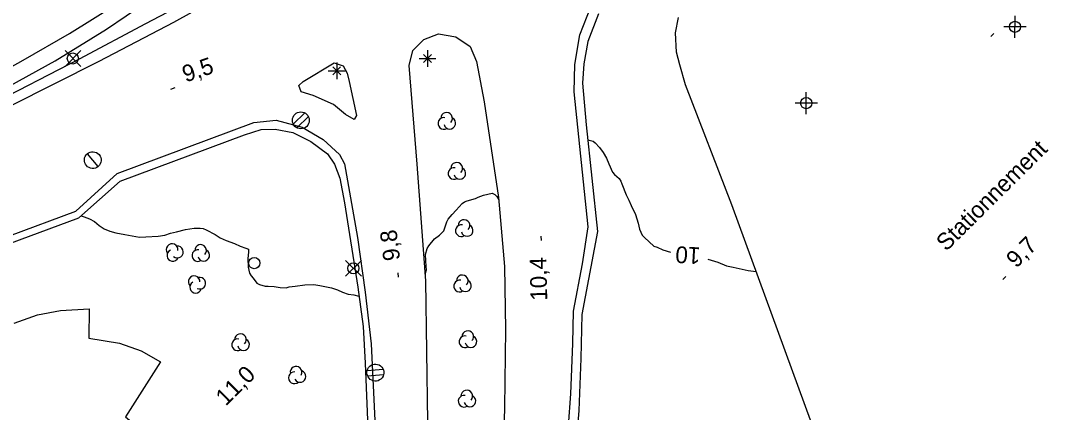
# Model space of a CAD drawing. Extents: x 381879 to 384696, y 5564785 to 5567594.
# Drawn here: x 383815.6 to 384000, y 5566230.8 to 5566301.1 of the extents above; entities that cross this region are included whole.
import ezdxf

# ---------------------------------------------------------------- set-up
doc = ezdxf.new("R2010")
doc.units = 0
for name, color, linetype in [('Niveau 1', 7, 'Continuous'), ('Niveau 21', 7, 'Continuous'), ('Niveau 22', 7, 'Continuous'), ('Niveau 3', 7, 'Continuous'), ('Niveau 31', 7, 'Continuous'), ('Niveau 36', 7, 'Continuous'), ('Niveau 44', 7, 'Continuous'), ('Niveau 52', 7, 'Continuous')]:
    doc.layers.add(name, color=color, linetype=linetype)

msp = doc.modelspace()

# ---------------------------------------------------------------- linework, layer by layer
at = {"layer": 'Niveau 1'}
for points in [[(383917.33, 5566279.72), (383918.3, 5566279.5), (383918.69, 5566279.18), (383919.44, 5566278.36), (383920.13, 5566277.45), (383920.72, 5566276.45), (383921.1, 5566275.41), (383921.8, 5566273.92), (383922.16, 5566273.52), (383922.96, 5566272.79), (383923.25, 5566272.33), (383923.44, 5566271.8), (383924.24, 5566269.83), (383924.73, 5566268.92), (383925.13, 5566267.94), (383925.88, 5566266.36), (383926.41, 5566264.76), (383926.62, 5566263.72), (383927.12, 5566262.62), (383927.54, 5566262.2), (383929.22, 5566260.67), (383929.8, 5566260.49), (383930.81, 5566259.99), (383932.18, 5566259.6)], [(383888.19, 5566255.61), (383888.39, 5566256.4), (383888.33, 5566257), (383888.24, 5566259.19), (383888.53, 5566260.23), (383888.81, 5566260.69), (383889.85, 5566261.95), (383890.75, 5566262.65), (383891.52, 5566263.43), (383891.72, 5566263.94), (383892.05, 5566265.01), (383892.32, 5566265.49), (383893, 5566266.32), (383893.75, 5566267.09), (383894.8, 5566268.29), (383895.22, 5566268.59), (383895.73, 5566268.77), (383897.22, 5566269.18), (383897.67, 5566269.42), (383898.66, 5566269.78), (383900.19, 5566270.17), (383900.69, 5566269.94), (383901.03, 5566269.53), (383901.4, 5566268.96)], [(383826.48, 5566266.07), (383826.99, 5566265.94), (383828, 5566265.54), (383828.87, 5566265.05), (383829.71, 5566264.35), (383830.59, 5566263.79), (383831.63, 5566263.34), (383832.67, 5566263.05), (383834.31, 5566262.73), (383836.97, 5566262.28), (383838.08, 5566262.31), (383840.26, 5566262.42), (383841.48, 5566262.63), (383842.52, 5566262.97), (383843.56, 5566263.2), (383845.19, 5566263.64), (383846.74, 5566263.89), (383847.82, 5566263.91), (383848.37, 5566263.81), (383848.89, 5566263.58), (383850.52, 5566262.76), (383851.42, 5566262.15), (383852.5, 5566261.7), (383853.98, 5566261.15), (383854.97, 5566260.66), (383856.04, 5566260.32), (383856.49, 5566260.1), (383856.47, 5566259.6), (383856.35, 5566258.47), (383856.45, 5566256.88), (383856.68, 5566255.83), (383856.97, 5566255.32), (383857.31, 5566254.92), (383857.98, 5566254.02), (383858.46, 5566253.78), (383859.48, 5566253.46), (383860.02, 5566253.48), (383861.1, 5566253.4), (383862.18, 5566253.23), (383863.26, 5566253.21), (383863.78, 5566253.35), (383864.85, 5566253.47), (383866.59, 5566253.74), (383868.22, 5566253.78), (383869.28, 5566253.6), (383871.4, 5566253.17), (383872.44, 5566252.81), (383873.38, 5566252.38), (383874.38, 5566252.07), (383875.41, 5566251.92), (383876.31, 5566251.7)], [(383938.9, 5566258.31), (383940.66, 5566257.8), (383942.21, 5566257.15), (383943.41, 5566256.88), (383946.12, 5566256.32), (383947.55, 5566256.14)]]:
    msp.add_lwpolyline(points, dxfattribs=at)
at = {"layer": 'Niveau 21'}
for p, q in [((383887.1, 5566294.3), (383890.1, 5566294.3)), ((383887.88, 5566293.58), (383889.3, 5566295)), ((383889.32, 5566293.6), (383887.88, 5566295)), ((383888.6, 5566295.8), (383888.6, 5566292.8)), ((383871.59, 5566291.38), (383873.01, 5566292.8)), ((383873.03, 5566291.4), (383871.59, 5566292.8)), ((383872.31, 5566293.6), (383872.31, 5566290.6)), ((383870.81, 5566292.1), (383873.81, 5566292.1))]:
    msp.add_line(p, q, dxfattribs=at)
for points in [[(383915.3, 5566106.7), (383911.13, 5566107.33), (383907.59, 5566109.64), (383905.66, 5566111.96), (383904.48, 5566114.9), (383904.17, 5566117.91), (383904.87, 5566125.53), (383908.96, 5566171.44), (383912.18, 5566208.66), (383913.49, 5566222.72), (383914.28, 5566234.18), (383914.69, 5566243.23), (383914.76, 5566249), (383916.38, 5566257.46), (383917.43, 5566264.12), (383914.93, 5566288.3), (383915.05, 5566293.22), (383915.95, 5566298.53), (383917.89, 5566303.54), (383922.17, 5566309.93), (383926.92, 5566314.19)], [(383813.8, 5566285.8), (383829.7, 5566293.8), (383843.1, 5566300.8), (383849.8, 5566304.5)], [(383888.67, 5566229.09), (383888.28, 5566254.43), (383886.75, 5566275.37), (383885.32, 5566293.02), (383885.96, 5566295.71), (383887.95, 5566297.73), (383890.57, 5566298.72), (383893.65, 5566298.21), (383896.23, 5566296.44), (383897.37, 5566293.79), (383898.77, 5566286.53), (383901.34, 5566269.36), (383902.39, 5566256.99), (383902.59, 5566245.74), (383902.43, 5566231.74), (383901.93, 5566214.47)], [(383874.57, 5566290.16), (383875.88, 5566284.1), (383875.44, 5566283.34), (383873.86, 5566284.28), (383871.73, 5566286.05), (383868.09, 5566287.69), (383865.92, 5566288.32), (383865.51, 5566289.43), (383866.29, 5566290.16), (383871.84, 5566293.5), (383873.5, 5566292.98), (383874.21, 5566291.68), (383874.57, 5566290.16)], [(383801.65, 5566258.1), (383825.5, 5566266.93), (383832.91, 5566273.7), (383857.47, 5566282.82), (383861.47, 5566283.25), (383866.14, 5566281.99), (383869.86, 5566279.79), (383872.79, 5566277.11), (383873.7, 5566275.4), (383876.05, 5566262.22), (383877.43, 5566252.38), (383878.49, 5566243.14), (383879.24, 5566228.17)]]:
    msp.add_lwpolyline(points, dxfattribs=at)
at = {"layer": 'Niveau 22'}
for points in [[(383848.33, 5566305.95), (383837.99, 5566300.49), (383826.09, 5566294.18), (383809.63, 5566285.67), (383777.07, 5566269.59), (383779.22, 5566271.73), (383785.84, 5566275.55), (383791.21, 5566278.1), (383801.04, 5566282.67), (383811.97, 5566288.44), (383821.82, 5566293.88), (383831.03, 5566299.55), (383838.07, 5566304.32)], [(383727.7, 5566247.41), (383769.97, 5566266.61), (383773.34, 5566267.89), (383774.2, 5566268.48), (383774.7, 5566270.96), (383776.48, 5566273.48), (383783.13, 5566277.03), (383788.89, 5566280.06), (383798.86, 5566284.89), (383807.69, 5566289.32), (383816.07, 5566293.98), (383824.37, 5566298.79), (383833.11, 5566304.2), (383833.6, 5566304.56)], [(383919.26, 5566302.33), (383917.35, 5566297.32), (383916.63, 5566293.36), (383916.38, 5566289.9), (383917.05, 5566282.39), (383919.07, 5566263.26), (383916.26, 5566248.38), (383916.09, 5566240.51), (383915.75, 5566231.2), (383914.78, 5566219.14), (383914.11, 5566212.11), (383913.05, 5566199.57), (383910.63, 5566174.59), (383908.36, 5566147.91), (383905.59, 5566116.74), (383906.33, 5566114.6), (383907.65, 5566111.92), (383909.1, 5566110.56), (383911.92, 5566108.89), (383914.7, 5566108.3)], [(383810.04, 5566259.82), (383826.08, 5566265.71), (383833.5, 5566272.31), (383855.76, 5566280.62), (383858.74, 5566281.57), (383861.26, 5566281.64), (383864.42, 5566281.04), (383867.7, 5566279.39), (383870.68, 5566277.21), (383871.94, 5566275.35), (383872.86, 5566272.85), (383873.69, 5566268.44), (383876.1, 5566253.3), (383877.04, 5566246.27), (383877.39, 5566239.66), (383877.95, 5566226.61)]]:
    msp.add_lwpolyline(points, dxfattribs=at)
at = {"layer": 'Niveau 3'}
for p, q in [((383989.62, 5566298.24), (383990.19, 5566298.81)), ((383842.59, 5566288.8), (383843.33, 5566289.11)), ((383909.05, 5566261.66), (383908.99, 5566262.46)), ((383883.38, 5566255.07), (383883.32, 5566255.87)), ((383991.77, 5566254.65), (383992.34, 5566255.22))]:
    msp.add_line(p, q, dxfattribs=at)
at = {"layer": 'Niveau 31'}
msp.add_lwpolyline([(383814.47, 5566246.86), (383818.65, 5566248.33), (383822.78, 5566249.12), (383827.93, 5566249.42), (383827.88, 5566244.19), (383833.36, 5566243.27), (383837.26, 5566241.89), (383840.7, 5566239.93), (383834.4, 5566230.03), (383836.81, 5566228.07), (383837.88, 5566226.52), (383838.82, 5566224.79), (383840.46, 5566225.48), (383846.51, 5566211.94), (383848.69, 5566212.96), (383850.52, 5566208.9), (383850.01, 5566208.67), (383850.93, 5566206.19), (383831.62, 5566197.65), (383829.69, 5566201.94), (383820.17, 5566197.47), (383812.99, 5566213.33)], dxfattribs=at)
at = {"layer": 'Niveau 36'}
for p, q in [((383993.97, 5566297.98), (383993.98, 5566301.96)), ((383995.97, 5566299.96), (383991.98, 5566299.98)), ((383826.4, 5566295.71), (383823.58, 5566292.89)), ((383826.4, 5566292.89), (383823.58, 5566295.71)), ((383956.53, 5566284.3), (383956.54, 5566288.28)), ((383958.53, 5566286.28), (383954.54, 5566286.3)), ((383866.57, 5566284.55), (383864.51, 5566282.51)), ((383865.17, 5566281.87), (383867.23, 5566283.91)), ((383829.51, 5566274.91), (383827.61, 5566277.23)), ((383876.73, 5566258.1), (383873.91, 5566255.28)), ((383876.73, 5566255.28), (383873.91, 5566258.1)), ((383880.64, 5566238.55), (383877.75, 5566238.32)), ((383877.84, 5566237.41), (383880.73, 5566237.64))]:
    msp.add_line(p, q, dxfattribs=at)
for centre, radius in [((383993.97, 5566299.98), 1), ((383824.98, 5566294.3), 1), ((383956.53, 5566286.3), 1), ((383865.88, 5566283.21), 1.52), ((383857.52, 5566257.62), 1), ((383875.31, 5566256.69), 1)]:
    msp.add_circle(centre, radius, dxfattribs=at)
for centre, major_axis, ratio in [((383828.55, 5566276.08), (-1.19, 0.92), 0.999876), ((383879.25, 5566237.98), (-1.21, 0.92), 0.999875)]:
    msp.add_ellipse(centre, major_axis=major_axis, ratio=ratio, dxfattribs=at)
at = {"layer": 'Niveau 44'}
for centre, major_axis, ratio, start_param, end_param in [((383891.53, 5566282.66), (-0.836, 0.629), 0.999875, 5.163765, 9.050341), ((383892.02, 5566283.58), (-0.836, 0.629), 0.999875, 3.020126, 6.959135), ((383892.58, 5566282.7), (-0.836, 0.629), 0.999875, 0.893509, 4.863384), ((383893.84, 5566274.6), (-0.836, 0.629), 0.999875, 3.020126, 6.959135), ((383893.35, 5566273.68), (-0.836, 0.629), 0.999875, 5.163765, 9.050341), ((383894.4, 5566273.72), (-0.836, 0.629), 0.999875, 0.893509, 4.863384), ((383895.15, 5566264.35), (-0.836, 0.629), 0.999875, 3.020126, 6.959135), ((383894.66, 5566263.43), (-0.836, 0.629), 0.999875, 5.163765, 9.050341), ((383895.71, 5566263.47), (-0.836, 0.629), 0.999875, 0.893509, 4.863384), ((383842.79, 5566260.03), (0.833, -0.633), 0.999875, 0.49115, 4.430159), ((383847.9, 5566259.88), (-0.836, 0.629), 0.999875, 3.020126, 6.959135), ((383842.91, 5566259), (0.833, -0.633), 0.999875, 2.63479, 6.521365), ((383843.75, 5566259.62), (0.833, -0.633), 0.999875, 4.647718, 8.617593), ((383847.41, 5566258.96), (-0.836, 0.629), 0.999875, 5.163765, 9.050341), ((383848.46, 5566259), (-0.836, 0.629), 0.999875, 0.893509, 4.863384), ((383894.84, 5566254.43), (-0.836, 0.629), 0.999875, 3.020126, 6.959135), ((383846.74, 5566254.28), (-0.83, 0.636), 0.999877, 3.752801, 7.722676), ((383847.02, 5566253.28), (-0.83, 0.636), 0.999877, 5.879418, 9.818427), ((383847.76, 5566254.01), (-0.83, 0.636), 0.999877, 1.739872, 5.626448), ((383894.35, 5566253.51), (-0.836, 0.629), 0.999875, 5.163765, 9.050341), ((383895.4, 5566253.55), (-0.836, 0.629), 0.999875, 0.893509, 4.863384), ((383855.04, 5566243.9), (-0.836, 0.629), 0.999875, 3.020126, 6.959135), ((383895.33, 5566243.52), (-0.836, 0.629), 0.999875, 5.163765, 9.050341), ((383895.82, 5566244.44), (-0.836, 0.629), 0.999875, 3.020126, 6.959135), ((383896.38, 5566243.56), (-0.836, 0.629), 0.999875, 0.893509, 4.863384), ((383854.55, 5566242.98), (-0.836, 0.629), 0.999875, 5.163765, 9.050341), ((383855.6, 5566243.02), (-0.836, 0.629), 0.999875, 0.893509, 4.863384), ((383865.02, 5566238.06), (-0.837, 0.627), 0.999875, 3.269179, 7.155754), ((383864.73, 5566237.06), (-0.837, 0.627), 0.999875, 5.282107, 9.251982), ((383865.74, 5566237.3), (-0.837, 0.627), 0.999875, 1.125539, 5.064548), ((383895.16, 5566232.86), (-0.836, 0.629), 0.999875, 5.163765, 9.050341), ((383895.65, 5566233.78), (-0.836, 0.629), 0.999875, 3.020126, 6.959135), ((383896.21, 5566232.9), (-0.836, 0.629), 0.999875, 0.893509, 4.863384)]:
    msp.add_ellipse(centre, major_axis=major_axis, ratio=ratio, start_param=start_param, end_param=end_param, dxfattribs=at)
at = {"layer": 'Niveau 52'}
msp.add_lwpolyline([(383925.16, 5566212.48), (383932.82, 5566213.91), (383935.93, 5566214.85), (383933.86, 5566220.37), (383957.52, 5566228.82), (383943.19, 5566268.07), (383934.89, 5566289.56), (383933.86, 5566293.14), (383933.26, 5566295.42), (383933.09, 5566298.9), (383933.64, 5566301.67)], dxfattribs=at)

# ---------------------------------------------------------------- texts
at = {"layer": 'Niveau 1'}
msp.add_text('10', height=3, rotation=176.6608, dxfattribs=at).set_placement((383937.62, 5566260.41))
at = {"layer": 'Niveau 3'}
for s, rotation, p in [('9,5  ', 18.8619, (383845.22, 5566289.98)), ('9,8', 97.2458, (383883.71, 5566258.22)), ('9,7', 44.7717, (383994.2, 5566256.6)), ('10,4', 91.3439, (383910.09, 5566250.91)), ('11,0', 44.7717, (383852.41, 5566231.87))]:
    msp.add_text(s, height=3, rotation=rotation, dxfattribs=at).set_placement(p)
at = {"layer": 'Niveau 52'}
msp.add_text('Stationnement', height=3, rotation=44.7717, dxfattribs=at).set_placement((383981.64, 5566259.61))

doc.saveas('drawing.dxf')
